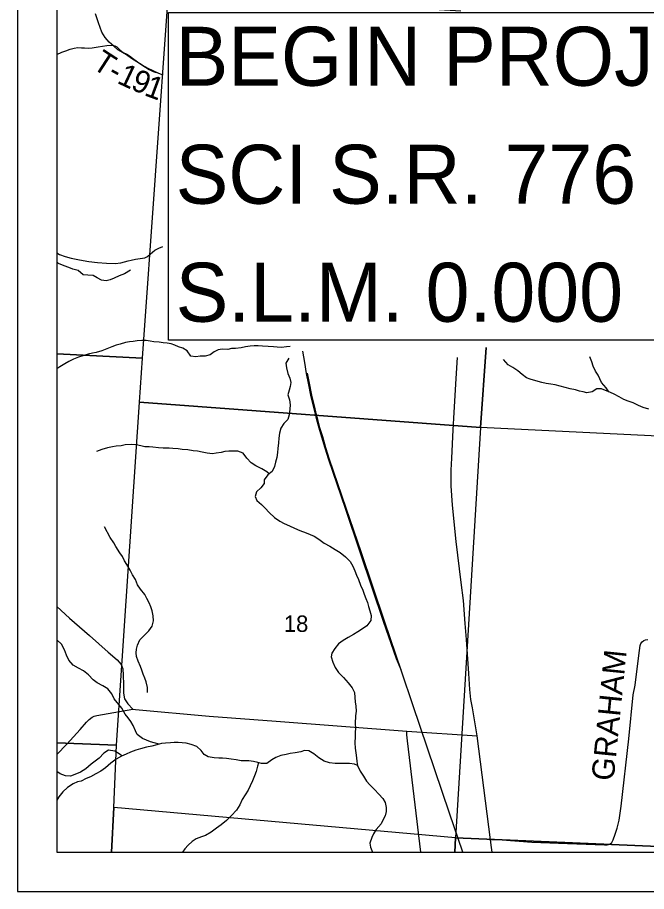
# Model space of a CAD drawing. Extents: x 0 to 40.8, y 0 to 22.
# Drawn here: x 2 to 3.599, y 14 to 16.222 of the extents above; entities that cross this region are included whole.
import ezdxf

# ---------------------------------------------------------------- set-up
doc = ezdxf.new("R2010")
doc.units = 0
for name, color, linetype in [('Default', 7, 'Continuous'), ('GM_X_County_Road', 7, 'Continuous'), ('GM_X_Minor_River', 7, 'Continuous'), ('GM_X_Rail_Line', 7, 'Continuous'), ('GM_X_Section', 7, 'Continuous'), ('GM_X_Section_Text', 7, 'Continuous'), ('GM_X_Township_Road', 7, 'Continuous'), ('GM_X_Township_Road_Text', 7, 'Continuous'), ('SH_Cut_Line', 7, 'Continuous'), ('SH_Data', 7, 'Continuous')]:
    doc.layers.add(name, color=color, linetype=linetype)

msp = doc.modelspace()

# ---------------------------------------------------------------- linework, layer by layer
at = {"layer": 'Default'}
for points in [[(2.1, 16.4387), (2.1, 14.1), (8.9, 14.1), (8.9, 16.9831), (7.7161, 17.0658), (7.7144, 17.066), (7.54, 17.0745), (7.4495, 17.0841), (6.9172, 17.1197), (6.1785, 17.166), (5.6278, 17.197), (5.3407, 17.2146), (4.8294, 17.2493), (4.5348, 17.2687), (3.4481, 17.3334), (3.1244, 17.3534), (2.8484, 17.3691), (2.8463, 17.3693), (2.4594, 17.3966), (2.4379, 17.0913), (2.3911, 16.4258)], [(2.3843, 16.2351), (3.9199, 16.2351), (3.9199, 15.4019), (2.3843, 15.4019)]]:
    msp.add_lwpolyline(points, close=True, dxfattribs=at)
at = {"layer": 'GM_X_County_Road'}
msp.add_line((2.9898, 14.4076), (3.1689, 14.3954), dxfattribs=at)
for points in [[(2.1, 16.4355), (2.1, 15.3674), (2.3175, 15.3564), (2.3841, 16.286), (2.3935, 16.4216)], [(2.1, 15.3674), (2.1, 14.3784), (2.2518, 14.3718), (2.3098, 15.2439), (2.3175, 15.3564)], [(3.9661, 14.1), (4.1612, 14.1), (4.2184, 15.1287), (3.1769, 15.1799), (3.1139, 14.1362)], [(2.1, 14.3784), (2.1, 14.1), (2.2392, 14.1), (2.245, 14.2139), (2.2518, 14.3718)], [(2.2392, 14.1), (3.1117, 14.1), (3.1139, 14.1362), (2.245, 14.2139)], [(3.1117, 14.1), (3.9661, 14.1), (3.1139, 14.1362)]]:
    msp.add_lwpolyline(points, close=True, dxfattribs=at)
for points in [[(3.2069, 14.1), (3.2053, 14.1121), (3.2025, 14.1317), (3.1689, 14.3954), (3.1563, 14.4667), (3.1527, 14.4885), (3.1501, 14.5134), (3.1472, 14.5541), (3.1411, 14.641), (3.138, 14.6817), (3.1337, 14.7402), (3.1276, 14.7854), (3.115, 14.89), (3.1057, 14.9819), (3.1028, 15.0318), (3.1027, 15.071), (3.1039, 15.102), (3.1078, 15.1735), (3.11, 15.218), (3.1156, 15.3042), (3.1187, 15.358)], [(2.1, 14.3485), (2.1251, 14.3745), (2.159, 14.4119), (2.1755, 14.4307), (2.1826, 14.4376), (2.1897, 14.443), (2.1953, 14.4458), (2.2019, 14.4475), (2.2304, 14.4529), (2.2934, 14.464), (2.2996, 14.4625), (2.487, 14.4458), (2.6574, 14.4333), (2.9898, 14.4076)], [(3.0251, 14.1), (2.9911, 14.3834), (2.9896, 14.3987), (2.9898, 14.4076)]]:
    msp.add_lwpolyline(points, dxfattribs=at)
at = {"layer": 'GM_X_Minor_River'}
for points in [[(2.37, 16.0754), (2.37, 16.0754), (2.359, 16.08), (2.3325, 16.0922), (2.317, 16.1006), (2.303, 16.1098), (2.2901, 16.1178), (2.2768, 16.127), (2.2666, 16.1335), (2.2549, 16.1403), (2.2451, 16.1495), (2.2329, 16.1594), (2.2227, 16.1716), (2.2141, 16.1849), (2.2062, 16.2088), (2.2017, 16.221), (2.1987, 16.2316)], [(2.287, 15.5801), (2.2718, 15.5703), (2.2588, 15.5651), (2.2459, 15.5594), (2.2357, 15.5553), (2.2258, 15.5526), (2.2133, 15.5542), (2.2023, 15.5603), (2.1921, 15.566), (2.1792, 15.5668), (2.1667, 15.568), (2.1542, 15.5787), (2.1406, 15.5822), (2.1307, 15.5867), (2.1186, 15.591), (2.1046, 15.5971), (2.1, 15.601)], [(2.6936, 15.3855), (2.6842, 15.3844), (2.6713, 15.383), (2.6603, 15.3842), (2.6505, 15.3849), (2.6372, 15.3854), (2.6232, 15.3866), (2.6122, 15.3874), (2.6015, 15.387), (2.5917, 15.3863), (2.5795, 15.3848), (2.5689, 15.3826), (2.5541, 15.3807), (2.5439, 15.3804), (2.5344, 15.3781), (2.5207, 15.3786), (2.5101, 15.3775), (2.4999, 15.3722), (2.49, 15.3646), (2.4771, 15.3613), (2.4642, 15.3609), (2.4535, 15.3598), (2.4407, 15.3614), (2.4316, 15.3747), (2.4202, 15.3812), (2.4096, 15.3846), (2.3998, 15.3889), (2.3903, 15.3923), (2.3805, 15.3942), (2.3706, 15.3954), (2.3604, 15.3966), (2.3467, 15.3974), (2.3369, 15.3993), (2.327, 15.4009), (2.3164, 15.4009), (2.3046, 15.4002), (2.2944, 15.3987), (2.2849, 15.3976), (2.2746, 15.3957), (2.261, 15.392), (2.2507, 15.3894), (2.2397, 15.3852), (2.2272, 15.3796), (2.2147, 15.3747), (2.1999, 15.3706), (2.1904, 15.3691), (2.1794, 15.3665), (2.1661, 15.3623), (2.1554, 15.3586), (2.1425, 15.3533), (2.1308, 15.3477), (2.1201, 15.342), (2.108, 15.3341), (2.1, 15.3291)], [(2.6902, 15.3556), (2.6826, 15.3435), (2.6841, 15.3313), (2.687, 15.3173), (2.6923, 15.3051), (2.6949, 15.2945), (2.6934, 15.2842), (2.6903, 15.2748), (2.6873, 15.2626), (2.6918, 15.2497), (2.6929, 15.2376), (2.6925, 15.2262), (2.6905, 15.2121), (2.6875, 15.2), (2.6772, 15.1898), (2.6692, 15.1784), (2.6661, 15.1652), (2.6646, 15.1526), (2.6634, 15.1405), (2.6618, 15.1261)], [(3.5033, 15.2701), (3.4963, 15.2807), (3.4849, 15.294), (3.48, 15.3035), (3.4759, 15.313), (3.4695, 15.3229), (3.4634, 15.3354), (3.4597, 15.3464), (3.4552, 15.359)], [(3.6046, 15.2264), (3.5906, 15.2302), (3.5788, 15.2356), (3.5652, 15.2421), (3.5523, 15.2463), (3.5413, 15.2509), (3.5296, 15.2578), (3.5171, 15.2646), (3.5072, 15.2685), (3.4845, 15.2777), (3.4731, 15.2781), (3.4606, 15.2705), (3.4477, 15.2679), (3.4378, 15.2702), (3.4284, 15.2725), (3.4189, 15.2752), (3.4049, 15.2783), (3.392, 15.2818), (3.3795, 15.2852), (3.367, 15.2879), (3.3556, 15.2899), (3.3438, 15.2918), (3.3332, 15.2938), (3.3177, 15.2984), (3.3037, 15.3022), (3.2938, 15.3064), (3.2829, 15.3148), (3.2719, 15.3239), (3.2594, 15.3327), (3.2477, 15.3392), (3.2352, 15.3529)], [(2.6402, 15.0623), (2.6336, 15.0673), (2.6215, 15.0746), (2.6063, 15.0822), (2.5938, 15.0903), (2.5832, 15.1021), (2.5734, 15.1142), (2.5605, 15.1192), (2.5473, 15.1196), (2.537, 15.1193), (2.5275, 15.1186), (2.5177, 15.1163), (2.5055, 15.1145), (2.496, 15.1126), (2.4824, 15.1142), (2.4691, 15.1173), (2.4574, 15.1196), (2.4468, 15.1208), (2.4327, 15.1231), (2.4187, 15.1239), (2.4085, 15.1254), (2.3948, 15.1263), (2.3853, 15.127), (2.3705, 15.1275), (2.3584, 15.1279), (2.3444, 15.1295), (2.3349, 15.1303), (2.3239, 15.1307), (2.3137, 15.133), (2.3015, 15.1353), (2.2902, 15.1369), (2.2739, 15.1358), (2.264, 15.1335), (2.2511, 15.1321), (2.2412, 15.131), (2.2287, 15.1283), (2.2147, 15.1238), (2.201, 15.119)], [(2.6618, 15.1261), (2.6606, 15.1158), (2.6591, 15.1033), (2.656, 15.0919), (2.653, 15.0802), (2.6472, 15.0677), (2.6362, 15.0594), (2.6271, 15.0469), (2.6267, 15.0374), (2.6183, 15.026), (2.6073, 15.0158), (2.6038, 15.0041), (2.6083, 14.9942), (2.6204, 14.9839), (2.6299, 14.9744), (2.6401, 14.9633), (2.6537, 14.9511), (2.667, 14.9412), (2.6776, 14.9359), (2.6912, 14.9294), (2.7044, 14.9236), (2.7181, 14.9179), (2.7336, 14.9118), (2.7438, 14.9076), (2.7541, 14.9037), (2.7662, 14.8957), (2.7798, 14.8858), (2.7938, 14.8778), (2.8074, 14.8698), (2.8207, 14.8617), (2.8339, 14.8507), (2.846, 14.8393), (2.8524, 14.8271), (2.8577, 14.8153), (2.8619, 14.8047), (2.8671, 14.7933), (2.872, 14.7792), (2.8777, 14.7663), (2.8814, 14.756), (2.8856, 14.7446), (2.8897, 14.7347), (2.8927, 14.7245), (2.8957, 14.7138), (2.8987, 14.7017), (2.8979, 14.6888), (2.888, 14.6759), (2.8747, 14.6665), (2.8652, 14.6604), (2.8538, 14.6533), (2.8409, 14.6457), (2.828, 14.6382), (2.8158, 14.6295), (2.8067, 14.6181), (2.7987, 14.606), (2.7975, 14.5965), (2.8013, 14.5832), (2.8077, 14.5699), (2.8164, 14.5566), (2.8285, 14.544), (2.8406, 14.5303), (2.8508, 14.5178), (2.8564, 14.5056), (2.8575, 14.4931), (2.8582, 14.4824), (2.8601, 14.471), (2.8608, 14.4585), (2.8597, 14.4464), (2.8588, 14.4274), (2.8596, 14.4149), (2.8584, 14.4046), (2.8584, 14.3944), (2.8579, 14.3784), (2.8587, 14.3648), (2.8605, 14.353), (2.862, 14.3401), (2.8627, 14.3302), (2.8646, 14.3203), (2.871, 14.3063), (2.8793, 14.2933), (2.8876, 14.2804), (2.8959, 14.2709), (2.9076, 14.2591), (2.919, 14.2473), (2.9288, 14.2366), (2.9345, 14.2267), (2.9371, 14.2138), (2.9374, 14.2032), (2.9344, 14.1926), (2.929, 14.1816), (2.9244, 14.1721), (2.9119, 14.1581), (2.905, 14.1467), (2.9004, 14.1373), (2.8959, 14.1232), (2.897, 14.113), (2.9023, 14.1)], [(2.3304, 14.5063), (2.3304, 14.5184), (2.327, 14.5329), (2.324, 14.5424), (2.3199, 14.5526), (2.3165, 14.5629), (2.3124, 14.5724), (2.3067, 14.5853), (2.3026, 14.5975), (2.3015, 14.607), (2.3023, 14.6165), (2.305, 14.6263), (2.3111, 14.64), (2.3221, 14.6509), (2.3339, 14.663), (2.3423, 14.6744), (2.3461, 14.6884), (2.345, 14.7006), (2.342, 14.7135), (2.3386, 14.7234), (2.3345, 14.734), (2.3288, 14.7454), (2.3235, 14.7549), (2.3126, 14.7686), (2.3054, 14.7797), (2.3001, 14.7933), (2.2922, 14.8048), (2.2866, 14.8173), (2.2783, 14.831), (2.2722, 14.8409), (2.2666, 14.8519), (2.2598, 14.8614), (2.2503, 14.877), (2.2447, 14.8865), (2.236, 14.9002), (2.2209, 14.9268)], [(2.3601, 14.3744), (2.3478, 14.3783), (2.338, 14.3803), (2.3277, 14.3845), (2.3175, 14.3891), (2.3043, 14.3994), (2.2997, 14.4089), (2.2945, 14.4222), (2.2884, 14.4321), (2.2813, 14.4416), (2.2737, 14.4511), (2.265, 14.4659), (2.2461, 14.4895), (2.2401, 14.5024), (2.2295, 14.515), (2.2167, 14.5226), (2.2023, 14.5307), (2.1924, 14.5379), (2.1807, 14.5512), (2.1678, 14.5611), (2.155, 14.568), (2.1417, 14.5757), (2.1308, 14.5878), (2.1247, 14.6012), (2.1191, 14.6148), (2.1123, 14.6285), (2.1, 14.6395)], [(2.8647, 14.3201), (2.857, 14.3242), (2.8441, 14.3254), (2.8339, 14.3258), (2.8077, 14.3259), (2.7933, 14.327), (2.7797, 14.3313), (2.7657, 14.3401), (2.7532, 14.35), (2.7403, 14.3576), (2.7297, 14.3584), (2.7202, 14.3554), (2.7058, 14.3524), (2.6929, 14.3506), (2.6834, 14.3487), (2.6693, 14.3457), (2.6564, 14.3404), (2.6466, 14.3348), (2.6336, 14.3257), (2.6204, 14.3254), (2.6109, 14.3277), (2.5999, 14.3308), (2.5878, 14.3319), (2.5783, 14.3324), (2.5684, 14.3324), (2.5555, 14.3351), (2.5434, 14.3367), (2.5316, 14.3378), (2.5214, 14.339), (2.5116, 14.3394), (2.5002, 14.3398), (2.485, 14.3422), (2.4748, 14.3487), (2.4672, 14.3582), (2.4559, 14.3685), (2.4415, 14.3735), (2.4286, 14.3769), (2.4187, 14.3777), (2.4081, 14.3785), (2.3986, 14.3785), (2.3892, 14.3782), (2.3759, 14.3775), (2.3664, 14.376), (2.3543, 14.373), (2.3414, 14.3696), (2.3284, 14.3674), (2.3129, 14.3629), (2.3007, 14.3591), (2.2871, 14.3539), (2.2764, 14.3494), (2.2647, 14.3445), (2.251, 14.3369), (2.2373, 14.326), (2.224, 14.3146), (2.2122, 14.3063), (2.1993, 14.2988), (2.1856, 14.2912), (2.175, 14.2871), (2.1621, 14.2807), (2.1526, 14.2788), (2.1412, 14.2739), (2.1275, 14.2641), (2.1153, 14.2535), (2.1051, 14.241), (2.1, 14.2324)], [(2.265, 14.3446), (2.2609, 14.3483), (2.2473, 14.3571), (2.2317, 14.359), (2.2199, 14.3515), (2.2078, 14.339), (2.1979, 14.331), (2.1869, 14.3235), (2.1735, 14.3121), (2.1602, 14.3031), (2.1458, 14.2974), (2.1348, 14.2933), (2.1219, 14.2941), (2.1087, 14.2991), (2.1, 14.3053)], [(2.6125, 14.3273), (2.6105, 14.319), (2.6066, 14.3053), (2.6024, 14.2939), (2.5971, 14.2818), (2.5917, 14.2685), (2.5864, 14.2576), (2.5784, 14.2454), (2.5715, 14.2337), (2.565, 14.2208), (2.5567, 14.2072), (2.5441, 14.1936), (2.5316, 14.1807), (2.5175, 14.1697), (2.5057, 14.1611), (2.492, 14.1512), (2.478, 14.1426), (2.4681, 14.1388), (2.454, 14.1339), (2.4438, 14.1271), (2.4339, 14.118), (2.4251, 14.1082), (2.4193, 14.1)]]:
    msp.add_lwpolyline(points, dxfattribs=at)
at = {"layer": 'GM_X_Rail_Line'}
for points in [[(2.9753, 14.5633), (2.9631, 14.5915), (2.9308, 14.6869), (2.8721, 14.8604), (2.8335, 14.9738), (2.7912, 15.0978), (2.7818, 15.1274), (2.7736, 15.1551), (2.7667, 15.178), (2.7612, 15.1992), (2.7572, 15.2149), (2.7535, 15.2309), (2.7461, 15.2617), (2.7396, 15.2921), (2.7348, 15.3173), (2.7302, 15.3452), (2.7253, 15.3739)], [(3.1322, 14.1), (3.0984, 14.1996), (3.0051, 14.4746), (2.9771, 14.558), (2.9331, 14.6877), (2.8744, 14.8612), (2.8358, 14.9745), (2.7935, 15.0986), (2.7841, 15.1281), (2.7759, 15.1558), (2.769, 15.1786), (2.7636, 15.1998), (2.7596, 15.2155), (2.7558, 15.2314), (2.7485, 15.2622), (2.742, 15.2926), (2.7372, 15.3177)]]:
    msp.add_lwpolyline(points, dxfattribs=at)
at = {"layer": 'GM_X_Section'}
for points in [[(3.1915, 15.3835), (3.1769, 15.1799), (2.3098, 15.2439), (2.3175, 15.3564), (2.3841, 16.286), (3.1268, 16.2394)], [(3.9129, 16.1794), (4.2989, 16.1489), (4.2184, 15.1287), (3.1769, 15.1799), (3.1915, 15.3835)]]:
    msp.add_lwpolyline(points, dxfattribs=at)
msp.add_lwpolyline([(2.3098, 15.2439), (3.1769, 15.1799), (3.1139, 14.1362), (2.245, 14.2139), (2.2518, 14.3718)], close=True, dxfattribs=at)
at = {"layer": 'GM_X_Township_Road'}
for points in [[(2.1, 16.1283), (2.1126, 16.1344), (2.123, 16.1377), (2.1339, 16.1416), (2.1441, 16.1444), (2.1533, 16.1456), (2.1624, 16.1449), (2.1706, 16.1446), (2.1802, 16.1444), (2.1896, 16.1451), (2.2049, 16.1474), (2.227, 16.1507), (2.24, 16.152), (2.2471, 16.1505), (2.2527, 16.1472), (2.2606, 16.1403), (2.2685, 16.1332), (2.2779, 16.1286), (2.2845, 16.1245), (2.2924, 16.1187), (2.3051, 16.1098), (2.3165, 16.1016), (2.3351, 16.0902), (2.3448, 16.0851), (2.3527, 16.0819)], [(2.1, 15.6235), (2.1071, 15.6197), (2.1208, 15.6141), (2.1366, 15.6103), (2.1579, 15.6057), (2.1811, 15.6017), (2.203, 15.5991), (2.2259, 15.5973), (2.2485, 15.5963), (2.2625, 15.5981), (2.2724, 15.6012), (2.2815, 15.6037), (2.2892, 15.6055), (2.2999, 15.608), (2.3116, 15.609), (2.3235, 15.6113), (2.3304, 15.6149), (2.3372, 15.6205), (2.3492, 15.6304), (2.3591, 15.6355), (2.3698, 15.6401)], [(2.1, 14.7246), (2.1325, 14.6952), (2.1834, 14.6508), (2.2309, 14.6084), (2.2537, 14.5888), (2.2632, 14.5768), (2.2678, 14.5658), (2.269, 14.5504), (2.2693, 14.5264), (2.2692, 14.5047), (2.2722, 14.4903), (2.2803, 14.4774), (2.2934, 14.464)], [(3.2025, 14.1317), (3.2213, 14.1319), (3.3072, 14.1258), (3.398, 14.122), (3.4924, 14.1184), (3.4988, 14.1184), (3.5056, 14.1205), (3.5107, 14.1248), (3.5145, 14.1312), (3.5196, 14.1459), (3.5247, 14.1607), (3.5295, 14.1815), (3.5344, 14.2166), (3.5539, 14.388), (3.5654, 14.4997), (3.57, 14.5246), (3.5763, 14.5729), (3.5812, 14.6131), (3.5829, 14.6251), (3.5847, 14.6306), (3.588, 14.6352), (3.5921, 14.6385), (3.5969, 14.6403), (3.6023, 14.6408)]]:
    msp.add_lwpolyline(points, dxfattribs=at)
at = {"layer": 'SH_Cut_Line'}
msp.add_lwpolyline([(2.1, 17.4153), (2.1, 14.1), (8.9, 14.1), (8.9, 16.9831), (7.7161, 17.0658), (7.7144, 17.066), (7.54, 17.0745), (7.4495, 17.0841), (6.9172, 17.1197), (6.1785, 17.166), (5.6278, 17.197), (5.3407, 17.2146), (4.8294, 17.2493), (4.5348, 17.2687), (3.4481, 17.3334), (3.1244, 17.3534), (2.8484, 17.3691), (2.8463, 17.3693), (2.4594, 17.3966)], close=True, dxfattribs=at)
at = {"layer": 'SH_Data'}
for p, q in [((2, 21), (2, 14)), ((2.1, 20.9), (2.1, 14.1)), ((2.1, 14.1), (8.9, 14.1)), ((2.1, 14.1), (2.1, 14.1)), ((2, 14), (9, 14))]:
    msp.add_line(p, q, dxfattribs=at)

# ---------------------------------------------------------------- texts
at = {"layer": 'Default'}
for s, p in [('BEGIN PROJECT', (2.4021, 16.0486)), ('SCI S.R. 776', (2.4021, 15.7486)), ('S.L.M. 0.000', (2.4021, 15.4486))]:
    msp.add_text(s, height=0.15, dxfattribs=at).set_placement(p)
at = {"layer": 'GM_X_Section_Text'}
msp.add_text('18', height=0.04186, rotation=0, dxfattribs=at).set_placement((2.6771, 14.66))
at = {"layer": 'GM_X_Township_Road_Text'}
for s, height, rotation, p in [('T', 0.0568, 327.022, (2.1871, 16.0952)), ('-', 0.0568, 330.8376, (2.2262, 16.0699)), ('1', 0.0568, 334.8235, (2.2505, 16.0566)), ('9', 0.0568, 338.1346, (2.2854, 16.0403)), ('1', 0.0568, 339.7471, (2.3195, 16.0252)), ('GRAHAM', 0.05682, 84.2588, (3.5153, 14.2797))]:
    msp.add_text(s, height=height, rotation=rotation, dxfattribs=at).set_placement(p)

doc.saveas('drawing.dxf')
